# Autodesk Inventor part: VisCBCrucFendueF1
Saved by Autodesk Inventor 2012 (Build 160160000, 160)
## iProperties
Created: 2013-08
Part Number: VisCBCrucFendueF1
Material: Default
Document SubType Name: Modeling
Designer: hilarion
Density: 1 g/cm^3
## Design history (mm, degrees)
node "VisCBCrucFendueF11"
node "VisCBCrucFendueF1"
node "Base1"
